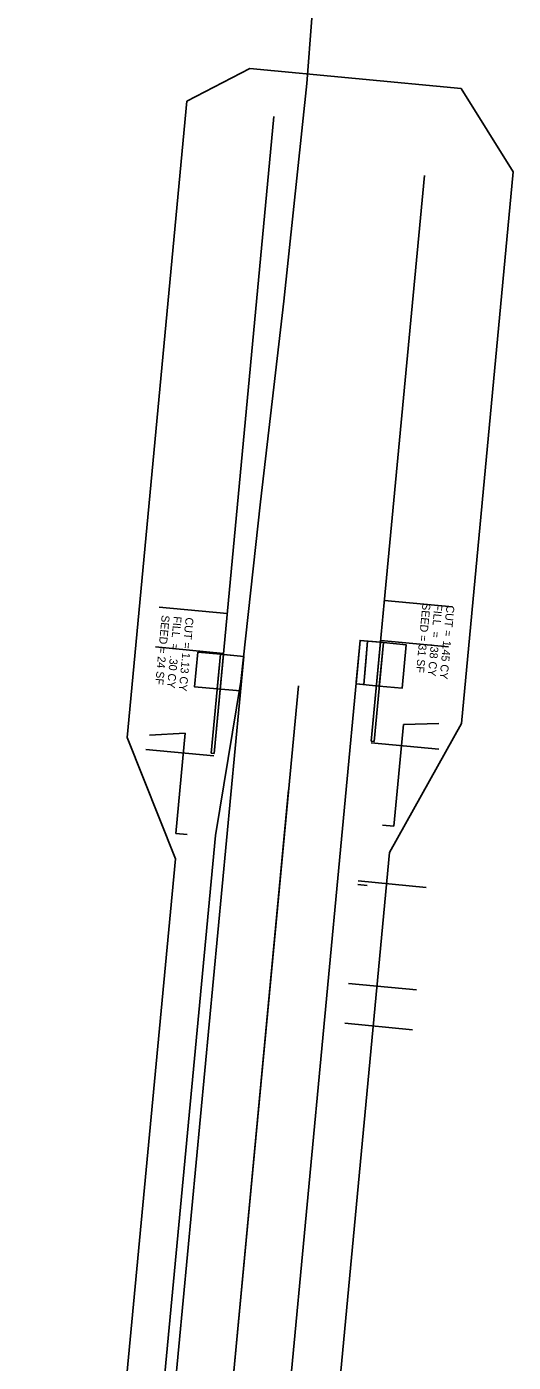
# Model space of a CAD drawing. Extents: x 1507088 to 1507206, y 518715 to 519811.
# Drawn here: x 1507120.6 to 1507205.7, y 519314.3 to 519547.9 of the extents above; entities that cross this region are included whole.
import ezdxf

# ---------------------------------------------------------------- set-up
doc = ezdxf.new("R2010")
doc.units = 0
for name, color, linetype in [('_CIVIL_CONSTRUCTION', 7, 'Continuous'), ('BR_P_Slab_Const_Joint', 7, 'Continuous'), ('BR_P_Slab_Object', 7, 'Continuous'), ('BR_X_Rail_Object', 7, 'Continuous'), ('BR_X_Sub_Foot_Hidden', 7, 'Continuous'), ('BR_X_Sub_Foot_Object', 7, 'Continuous'), ('BR_X_Sub_Hidden', 7, 'Continuous'), ('BR_X_Sub_Object', 7, 'Continuous'), ('Default', 7, 'Continuous'), ('RW_X_CL', 7, 'Continuous'), ('RW_X_Esmt_SH', 7, 'Continuous'), ('RW_X_Fee_WL', 7, 'Continuous'), ('SC_Scratch2', 7, 'Continuous'), ('SV_P_Control_Cells_Set', 7, 'Continuous')]:
    doc.layers.add(name, color=color, linetype=linetype)

msp = doc.modelspace()

# ---------------------------------------------------------------- linework, layer by layer
at = {"layer": '_CIVIL_CONSTRUCTION'}
for p, q in [((1507180.85, 519422.93), (1507182.47, 519440.23)), ((1507182.97, 519440.18), (1507181.35, 519422.88)), ((1507182.47, 519440.23), (1507182.97, 519440.18)), ((1507152.86, 519420.84), (1507154.49, 519438.14)), ((1507154.99, 519438.1), (1507153.36, 519420.8)), ((1507154.49, 519438.14), (1507154.99, 519438.1)), ((1507181.35, 519422.88), (1507180.85, 519422.93)), ((1507153.36, 519420.8), (1507152.86, 519420.84))]:
    msp.add_line(p, q, dxfattribs=at)
at = {"layer": 'BR_P_Slab_Const_Joint'}
msp.add_line((1507168.11, 519432.6), (1507136.62, 519097.51), dxfattribs=at)
at = {"layer": 'BR_P_Slab_Object'}
for p, q in [((1507178.91, 519440.56), (1507146.18, 519092.35)), ((1507158.56, 519437.76), (1507125.83, 519089.55))]:
    msp.add_line(p, q, dxfattribs=at)
at = {"layer": 'BR_X_Rail_Object'}
for p, q in [((1507182.47, 519440.23), (1507178.91, 519440.56)), ((1507154.99, 519438.1), (1507158.55, 519437.76))]:
    msp.add_line(p, q, dxfattribs=at)
at = {"layer": 'BR_X_Sub_Foot_Hidden'}
for p, q in [((1507186.48, 519425.86), (1507184.81, 519408.08)), ((1507192.7, 519426.04), (1507186.48, 519425.86)), ((1507142.06, 519424), (1507148.34, 519424.35)), ((1507148.34, 519424.35), (1507146.69, 519406.81)), ((1507184.81, 519408.08), (1507182.82, 519408.26)), ((1507146.69, 519406.81), (1507148.68, 519406.62))]:
    msp.add_line(p, q, dxfattribs=at)
at = {"layer": 'BR_X_Sub_Foot_Object'}
for p, q in [((1507195.04, 519446.41), (1507183.16, 519447.53)), ((1507155.66, 519445.26), (1507143.78, 519446.38)), ((1507194.38, 519439.44), (1507182.51, 519440.56)), ((1507155.01, 519438.29), (1507143.13, 519439.41)), ((1507153.32, 519420.37), (1507141.45, 519421.49)), ((1507192.7, 519421.52), (1507180.82, 519422.64)), ((1507190.43, 519397.37), (1507178.55, 519398.49)), ((1507188.74, 519379.45), (1507176.87, 519380.57)), ((1507188.09, 519372.48), (1507176.21, 519373.6))]:
    msp.add_line(p, q, dxfattribs=at)
at = {"layer": 'BR_X_Sub_Hidden'}
msp.add_line((1507180.15, 519397.71), (1507178.49, 519397.86), dxfattribs=at)
at = {"layer": 'BR_X_Sub_Object'}
msp.add_lwpolyline([(1507124.08, 519080.11), (1507126.46, 519107.76), (1507125.57, 519109.49), (1507125.65, 519114.5), (1507126.85, 519122.3), (1507153.61, 519406.42), (1507158.07, 519433.38), (1507161.5, 519464.79), (1507165.54, 519499.89), (1507169.61, 519537.99), (1507170.44, 519549.37), (1507169.66, 519552.48), (1507172.98, 519586.6), (1507174.76, 519590.96), (1507177.32, 519614.86), (1507180.87, 519647.04), (1507184.19, 519678.45), (1507187.3, 519710.95), (1507190.97, 519746.83), (1507194.45, 519778.56), (1507197.67, 519811.38)], dxfattribs=at)
at = {"layer": 'Default'}
msp.add_line((1507133.65, 519065.93), (1507166.4, 519414.4), dxfattribs=at)
for points in [[(1507178.19, 519432.95), (1507178.91, 519440.56), (1507180.2, 519440.44), (1507179.54, 519432.83)], [(1507178.91, 519440.56), (1507182.97, 519440.18), (1507182.26, 519432.57), (1507178.19, 519432.95)], [(1507182.97, 519440.18), (1507186.95, 519439.81), (1507186.24, 519432.2), (1507182.26, 519432.57)], [(1507182.97, 519440.18), (1507186.95, 519439.81), (1507186.24, 519432.2), (1507182.26, 519432.57)], [(1507150.51, 519438.52), (1507154.49, 519438.14), (1507153.92, 519432.1), (1507149.94, 519432.47)], [(1507150.51, 519438.52), (1507154.49, 519438.14), (1507153.92, 519432.1), (1507149.94, 519432.47)], [(1507158.55, 519437.76), (1507157.99, 519431.72), (1507153.92, 519432.1), (1507154.49, 519438.14)]]:
    msp.add_lwpolyline(points, close=True, dxfattribs=at)
msp.add_lwpolyline([(1507179.54, 519432.83), (1507179.89, 519436.79), (1507180.2, 519440.44)], dxfattribs=at)
at = {"layer": 'RW_X_CL'}
for p, q in [((1507178.22, 519433.28), (1507178.91, 519440.56)), ((1507158, 519431.91), (1507158.55, 519437.76))]:
    msp.add_line(p, q, dxfattribs=at)
at = {"layer": 'RW_X_Esmt_SH'}
for p, q in [((1507159.6, 519540.59), (1507148.6, 519534.87)), ((1507159.6, 519540.59), (1507196.6, 519537.11)), ((1507196.6, 519537.11), (1507205.69, 519522.53)), ((1507138.14, 519423.59), (1507148.6, 519534.87)), ((1507205.69, 519522.53), (1507196.62, 519426.03)), ((1507196.62, 519426.03), (1507184.04, 519403.45)), ((1507146.61, 519402.35), (1507138.14, 519423.59)), ((1507146.61, 519402.35), (1507120.6, 519125.64)), ((1507184.04, 519403.45), (1507158.11, 519127.49))]:
    msp.add_line(p, q, dxfattribs=at)
at = {"layer": 'RW_X_Fee_WL'}
for p, q in [((1507163.83, 519532.18), (1507155.64, 519445.07)), ((1507155.64, 519445.07), (1507153.36, 519420.8))]:
    msp.add_line(p, q, dxfattribs=at)
at = {"layer": 'SV_P_Control_Cells_Set'}
for p, q in [((1507190.15, 519521.87), (1507183.13, 519447.2)), ((1507183.13, 519447.2), (1507180.85, 519422.93))]:
    msp.add_line(p, q, dxfattribs=at)

# ---------------------------------------------------------------- texts
at = {"layer": 'SC_Scratch2'}
for s, p in [('SEED = 31 SF', (1507189.83, 519447.13)), ('FILL  =  .38 CY', (1507191.92, 519446.94)), ('SEED = 24 SF', (1507144.22, 519445.02)), ('FILL  =  .30 CY', (1507146.31, 519444.83)), ('CUT =', (1507148.4, 519444.63)), ('CUT =', (1507194.02, 519446.74)), (' 1.45 CY', (1507193.48, 519441.09)), (' 1.13 CY', (1507147.87, 519438.98))]:
    msp.add_text(s, height=1.4, rotation=264.631, dxfattribs=at).set_placement(p)

doc.saveas('drawing.dxf')
